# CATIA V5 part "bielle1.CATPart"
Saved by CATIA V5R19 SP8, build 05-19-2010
Part number: bielle1
Publications: "axe1", "axeA", "axeroue", "axeB"
Bounding box of the stored display mesh (mm): x -20 to 20, y -80 to -80, z -120 to 80
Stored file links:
  C:\Users\rcousturie\Desktop\EU_thinkMotion\iao\IAO_MMS_Groupe1\flamrini\Lamrini_projet_IAO2011\Lamrini_projet_IAO2011\projet_iao_traindatterrissage\projet_iao_traindatterrissage\bielle1.CATPart
  C:\Users\rcousturie\Desktop\EU_thinkMotion\iao\IAO_MMS_Groupe1\flamrini\Lamrini_projet_IAO2011\Lamrini_projet_IAO2011\projet_iao_traindatterrissage\projet_iao_traindatterrissage\Part1.CATPart
  C:\Users\rcousturie\Desktop\EU_thinkMotion\iao\IAO_MMS_Groupe1\flamrini\Lamrini_projet_IAO2011\Lamrini_projet_IAO2011\projet_iao_traindatterrissage\projet_iao_traindatterrissage\squelettetrain.CATProduct
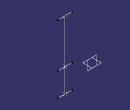
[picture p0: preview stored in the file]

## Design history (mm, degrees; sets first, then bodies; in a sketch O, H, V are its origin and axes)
Set1
  Point1 "PointA": linked copy from another document
  Point2: linked copy from another document
  Plane1: linked copy from another document
  Point3 "PointB": linked copy from another document
Set2
  Line1 "axe1": type PtPt, FirstPoint Point1, SecondPoint Point2
  Line2 "axeA": type PtDir, RefPoint Point1, Direction Plane1, Start -20, End 20
  Line3 "axeroue": type PtDir, RefPoint Point2, Direction Plane1, Start -20, End 20
  Line4 "axeB": type PtDir, RefPoint Point3, Direction Plane1, Start -20, End 20
Body1 (main body)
